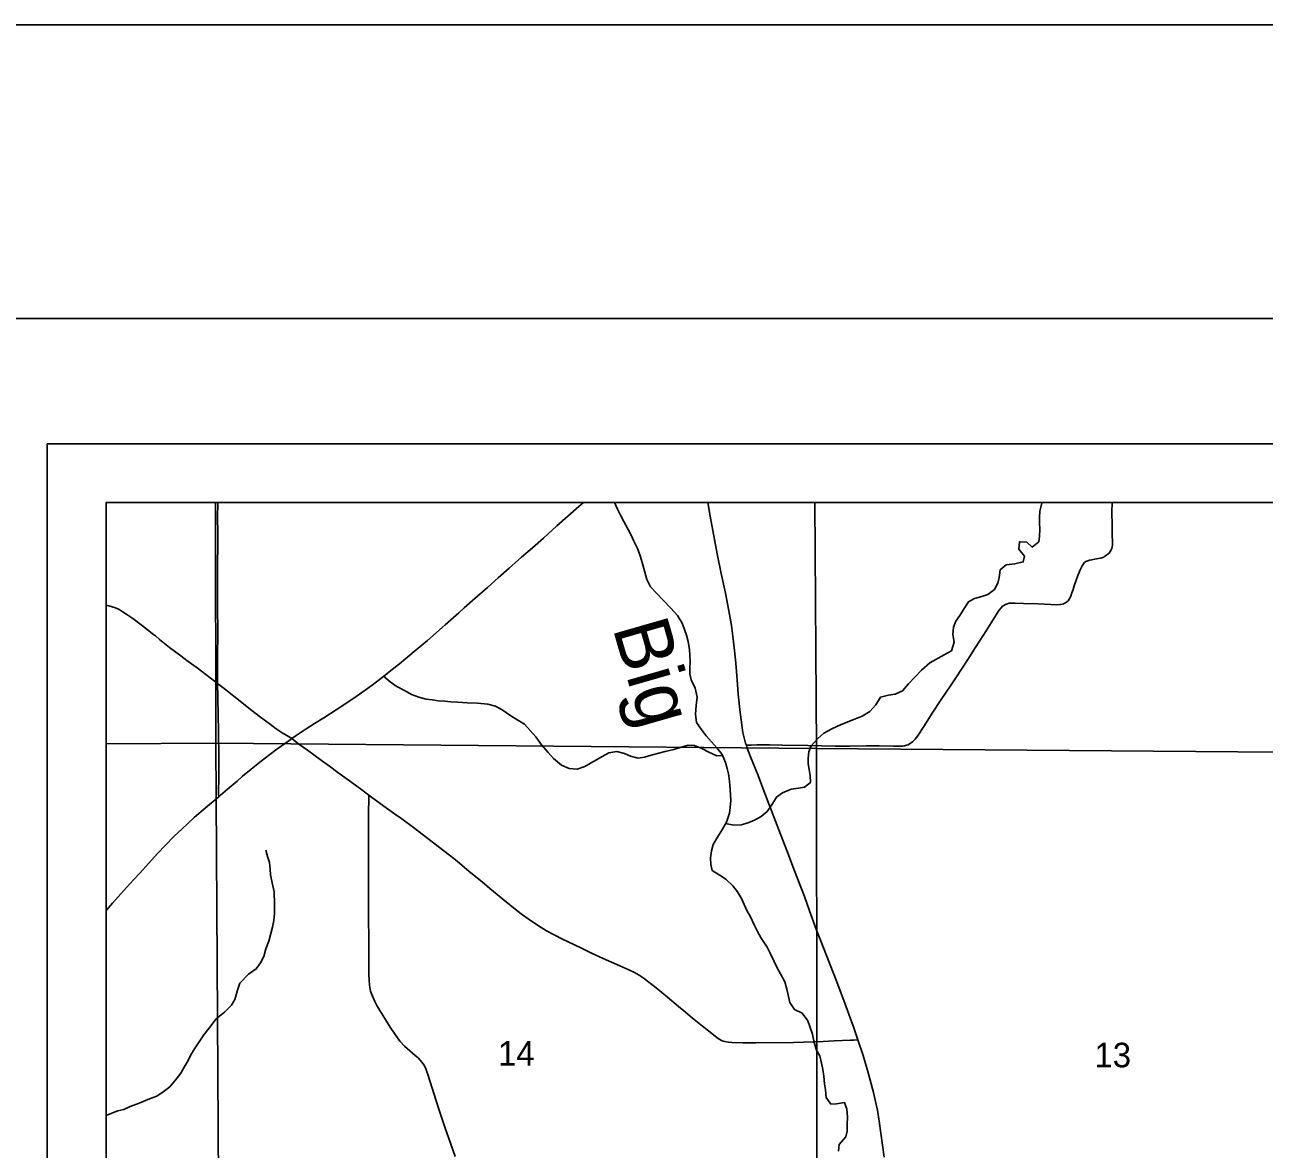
# Model space of a CAD drawing. Extents: x 0 to 34, y 0 to 22.
# Drawn here: x 1.722 to 3.831, y 20.086 to 22 of the extents above; entities that cross this region are included whole.
import ezdxf

# ---------------------------------------------------------------- set-up
doc = ezdxf.new("R2010")
doc.units = 0
for name, color, linetype in [('GM_X_County_Road', 7, 'Continuous'), ('GM_X_County_Road_Text', 7, 'Continuous'), ('GM_X_Interchange_Ramps', 7, 'Continuous'), ('GM_X_State_Location', 7, 'Continuous'), ('GM_X_State_Route', 7, 'Continuous'), ('GM_X_Township_Road_Text', 7, 'Continuous'), ('SH_Border', 7, 'Continuous'), ('SH_Cut_Line', 7, 'Continuous'), ('SH_Data', 7, 'Continuous')]:
    doc.layers.add(name, color=color, linetype=linetype)

msp = doc.modelspace()

# ---------------------------------------------------------------- linework, layer by layer
at = {"layer": 'GM_X_County_Road'}
for points in [[(1.8602, 20.4926), (1.8713, 20.5049), (1.9004, 20.5371), (1.917, 20.5554), (1.9481, 20.5897), (1.9609, 20.6032), (1.9763, 20.6186), (1.9897, 20.6315), (1.9988, 20.64), (2.0102, 20.6505), (2.0218, 20.6608), (2.036, 20.6728), (2.052, 20.6861), (2.055, 20.6886), (2.0667, 20.6986), (2.0832, 20.7127), (2.0926, 20.7208), (2.1069, 20.7327), (2.1239, 20.7463), (2.1387, 20.7577), (2.1511, 20.767), (2.1711, 20.7814), (2.1762, 20.7849), (2.1838, 20.7902), (2.1993, 20.8006), (2.2151, 20.8106), (2.2309, 20.8204), (2.2519, 20.8337), (2.27, 20.8456), (2.2878, 20.858), (2.3129, 20.8761), (2.3351, 20.893), (2.3449, 20.9006), (2.3595, 20.9122), (2.3881, 20.936), (2.407, 20.9522), (2.4373, 20.9788), (2.4513, 20.9911), (2.4606, 20.9993), (2.4699, 21.0075), (2.4837, 21.0198), (2.5091, 21.0423), (2.5277, 21.0586), (2.5463, 21.075), (2.5672, 21.0935), (2.5859, 21.1099), (2.6045, 21.1263), (2.6275, 21.1471), (2.6459, 21.1638), (2.6647, 21.1801), (2.6725, 21.1866)], [(2.9413, 20.8128), (2.9391, 20.8295), (2.936, 20.8604), (2.934, 20.8852), (2.9319, 20.9131), (2.9299, 20.9347), (2.9271, 20.9593), (2.9243, 20.9777), (2.9201, 21.0022), (2.9142, 21.0327), (2.9072, 21.0661), (2.9004, 21.0996), (2.888, 21.1636), (2.884, 21.1866)], [(3.0574, 20.4918), (3.0485, 20.5163), (3.0318, 20.5597), (3.0186, 20.5946), (3.0053, 20.6295), (2.9798, 20.6962), (2.9697, 20.7223), (2.9568, 20.7539), (2.9514, 20.7685), (2.9498, 20.7737), (2.9485, 20.7774), (2.9461, 20.7865), (2.9441, 20.7956), (2.942, 20.8079), (2.9413, 20.8128)], [(3.1397, 20.2723), (3.1327, 20.2924), (3.1158, 20.3391), (3.1025, 20.3739), (3.0812, 20.429), (3.0687, 20.4608), (3.0574, 20.4918)], [(3.1846, 20.0724), (3.1759, 20.1339), (3.1729, 20.1522), (3.1698, 20.1674), (3.1661, 20.1825), (3.1563, 20.2184), (3.1485, 20.2453), (3.1397, 20.2723)]]:
    msp.add_lwpolyline(points, dxfattribs=at)
at = {"layer": 'GM_X_County_Road_Text'}
for points in [[(2.7254, 21.1866), (2.7305, 21.1757), (2.7358, 21.1655), (2.7416, 21.1545), (2.7488, 21.1408), (2.7538, 21.131), (2.7584, 21.1212), (2.7649, 21.1075), (2.7699, 21.0943), (2.7737, 21.0806), (2.7772, 21.0685), (2.7803, 21.056), (2.7868, 21.0431), (2.7974, 21.0321), (2.8081, 21.0208), (2.8214, 21.0068), (2.8325, 20.9947), (2.8405, 20.9814), (2.8443, 20.9708), (2.8481, 20.961), (2.8508, 20.9503), (2.8532, 20.9363), (2.8536, 20.9268), (2.854, 20.9154), (2.8537, 20.9052), (2.8537, 20.8953), (2.856, 20.8847), (2.8625, 20.8707), (2.866, 20.8555), (2.8646, 20.8411), (2.8635, 20.8267), (2.8651, 20.8123), (2.8727, 20.8009), (2.8814, 20.7896), (2.8906, 20.7797), (2.8997, 20.7691), (2.9085, 20.7578), (2.9142, 20.7445), (2.9169, 20.7343), (2.9192, 20.7248), (2.9212, 20.7127), (2.9224, 20.6982), (2.9232, 20.6793), (2.9225, 20.6679), (2.921, 20.658), (2.9158, 20.6428), (2.909, 20.6306), (2.9007, 20.6173), (2.8936, 20.6044), (2.8906, 20.5941), (2.8888, 20.582), (2.8896, 20.5706), (2.8919, 20.5604), (2.9033, 20.5528), (2.9151, 20.5457), (2.9269, 20.5343), (2.9349, 20.5241), (2.9414, 20.5127)], [(2.9145, 20.6405), (2.9283, 20.6376), (2.9416, 20.6384), (2.9526, 20.6414), (2.9628, 20.6453), (2.9753, 20.6522), (2.9851, 20.6609), (2.9934, 20.6723), (3.0013, 20.6853), (3.0111, 20.6929), (3.0262, 20.699), (3.0383, 20.7006), (3.0486, 20.7021), (3.0588, 20.7102), (3.0587, 20.7223), (3.0568, 20.7322), (3.0548, 20.742), (3.0548, 20.7519), (3.0559, 20.7625), (3.0604, 20.7724), (3.0713, 20.7853), (3.0819, 20.7941), (3.0963, 20.8021), (3.1099, 20.8083), (3.1197, 20.8125), (3.133, 20.8175), (3.147, 20.8232), (3.1602, 20.8308), (3.17, 20.8426), (3.1783, 20.8556), (3.1919, 20.859), (3.2029, 20.8606), (3.2158, 20.8663), (3.2259, 20.8781), (3.2369, 20.89), (3.2478, 20.9014), (3.2618, 20.914), (3.2864, 20.9273), (3.2992, 20.9342), (3.3037, 20.949), (3.301, 20.9619), (3.3025, 20.9748), (3.3062, 20.9847), (3.313, 20.9946), (3.3217, 21.0083), (3.3277, 21.0178), (3.3383, 21.0235), (3.3508, 21.027), (3.361, 21.0301), (3.3719, 21.0385), (3.3779, 21.0495), (3.3802, 21.059), (3.382, 21.0723), (3.3918, 21.0807), (3.4066, 21.0823), (3.421, 21.0857), (3.4229, 21.0956), (3.4133, 21.1073), (3.4144, 21.1199), (3.4269, 21.1195), (3.4364, 21.1108), (3.4474, 21.12), (3.4485, 21.1298), (3.4492, 21.1412), (3.4488, 21.1515), (3.4487, 21.1621), (3.4491, 21.172), (3.4528, 21.1857), (3.4535, 21.1866)], [(2.3323, 20.891), (2.3436, 20.8815), (2.3539, 20.8743), (2.3694, 20.8663), (2.3801, 20.8602), (2.3926, 20.8557), (2.4047, 20.8522), (2.4157, 20.8507), (2.4256, 20.8492), (2.4366, 20.8484), (2.4472, 20.8477), (2.459, 20.8469), (2.4746, 20.8461), (2.4924, 20.8454), (2.5099, 20.8438), (2.5228, 20.8404), (2.5345, 20.8339), (2.5493, 20.8237), (2.5611, 20.8165), (2.5725, 20.8096)], [(2.9092, 20.7562), (2.8994, 20.7558), (2.8857, 20.7619), (2.874, 20.7683), (2.8614, 20.7732), (2.8508, 20.7735), (2.8387, 20.7704), (2.8262, 20.7666), (2.8114, 20.7631), (2.8008, 20.7604), (2.788, 20.7566), (2.7766, 20.7535), (2.7656, 20.7519), (2.7524, 20.7549), (2.7425, 20.7594), (2.7292, 20.7628), (2.716, 20.7605), (2.7046, 20.7543), (2.6948, 20.7486), (2.6846, 20.7429), (2.6747, 20.7375), (2.6619, 20.7329), (2.6482, 20.734), (2.6353, 20.7397), (2.6216, 20.751), (2.6125, 20.7612), (2.6011, 20.7744), (2.5915, 20.7881), (2.5725, 20.8096)], [(1.8602, 20.1435), (1.8672, 20.1462), (1.8801, 20.1511), (1.8903, 20.1538), (1.901, 20.1587), (1.9165, 20.1644), (1.934, 20.1716), (1.9465, 20.1761), (1.9575, 20.1837), (1.9686, 20.1921), (1.9796, 20.2054), (1.9872, 20.2152), (1.9933, 20.2255), (1.9997, 20.2369), (2.0047, 20.2464), (2.0108, 20.2566), (2.0267, 20.2805), (2.0351, 20.2912), (2.0477, 20.3079), (2.0617, 20.3192), (2.0739, 20.331), (2.0796, 20.3409), (2.0838, 20.3568), (2.0876, 20.3686), (2.1028, 20.3838), (2.1157, 20.3929), (2.1233, 20.4031), (2.1286, 20.4138), (2.1324, 20.4271), (2.137, 20.44), (2.1408, 20.4533), (2.1435, 20.4639), (2.1458, 20.4753), (2.1469, 20.4874), (2.147, 20.5034), (2.1462, 20.5239), (2.1428, 20.5395), (2.1398, 20.5531), (2.1394, 20.5626), (2.1383, 20.574), (2.1349, 20.5843), (2.1319, 20.5953)], [(2.9414, 20.5127), (2.946, 20.5025), (2.9509, 20.4923), (2.9567, 20.4813), (2.9632, 20.468), (2.9689, 20.4567), (2.975, 20.4453), (2.9853, 20.4302), (2.9906, 20.4196), (2.9968, 20.4067), (3.0025, 20.3946), (3.0078, 20.3847), (3.0151, 20.3707), (3.0193, 20.3563), (3.0217, 20.3461), (3.0236, 20.3358), (3.0316, 20.3241), (3.0449, 20.3177), (3.0544, 20.3045), (3.0579, 20.295), (3.0625, 20.2817), (3.0652, 20.2677), (3.0694, 20.2548), (3.0751, 20.245), (3.0778, 20.2324), (3.0802, 20.2218), (3.0817, 20.2101), (3.0829, 20.1975), (3.0845, 20.1873), (3.0857, 20.174), (3.0937, 20.1627), (3.1031, 20.1631), (3.1168, 20.1654), (3.121, 20.1544), (3.1218, 20.1411), (3.1211, 20.1282), (3.1212, 20.1165), (3.1193, 20.107), (3.108, 20.094), (3.1069, 20.0826)]]:
    msp.add_lwpolyline(points, dxfattribs=at)
at = {"layer": 'GM_X_Interchange_Ramps'}
for points in [[(2.0499, 20.8787), (2.0498, 20.8794), (2.0498, 20.8918), (2.05, 20.9042), (2.05, 20.9321), (2.0503, 20.9569), (2.0502, 20.9816), (2.0501, 20.994), (2.0501, 21.0096), (2.0501, 21.0655), (2.05, 21.0872), (2.0503, 21.1089), (2.0503, 21.1377), (2.0501, 21.1596), (2.0502, 21.1866)], [(2.9498, 20.7737), (2.9583, 20.774), (2.9676, 20.7743), (2.9893, 20.7742), (3.011, 20.7736), (3.0545, 20.773), (3.1011, 20.7722), (3.126, 20.7723), (3.1539, 20.7726), (3.1756, 20.7726), (3.2005, 20.7722), (3.2098, 20.772), (3.216, 20.7723), (3.2191, 20.7728), (3.2221, 20.7735), (3.225, 20.7746), (3.2277, 20.776), (3.2303, 20.7777), (3.2328, 20.7796), (3.235, 20.7817), (3.2371, 20.784), (3.2409, 20.789), (3.2528, 20.8072), (3.2663, 20.8281), (3.2816, 20.8515), (3.2972, 20.8746), (3.3075, 20.8901), (3.3161, 20.9032), (3.3279, 20.9215), (3.3381, 20.9376), (3.3478, 20.9527), (3.358, 20.9684), (3.3665, 20.9821), (3.3747, 20.9955), (3.3797, 21.0031), (3.3834, 21.0077), (3.3859, 21.0101), (3.3882, 21.0116), (3.3908, 21.0131), (3.394, 21.0143), (3.3969, 21.0152), (3.3999, 21.0157), (3.4065, 21.0156), (3.4216, 21.0149), (3.4463, 21.0141), (3.4682, 21.0133), (3.4782, 21.0127), (3.4839, 21.0132), (3.487, 21.0138), (3.4897, 21.0144), (3.4931, 21.0159), (3.4952, 21.0176), (3.4973, 21.0195), (3.4993, 21.0221), (3.5008, 21.0249), (3.5019, 21.0276), (3.5039, 21.0333), (3.506, 21.039), (3.5078, 21.045), (3.5139, 21.0625), (3.5185, 21.0736), (3.5201, 21.0767), (3.5214, 21.0792), (3.523, 21.082), (3.5253, 21.0845), (3.5278, 21.0862), (3.531, 21.0877), (3.5338, 21.0888), (3.5378, 21.0895), (3.5427, 21.0906), (3.552, 21.0919), (3.555, 21.0927), (3.5579, 21.094), (3.56, 21.0955), (3.5628, 21.0973), (3.5653, 21.0993), (3.5671, 21.1008), (3.569, 21.1032), (3.5707, 21.1062), (3.5719, 21.1085), (3.5723, 21.1112), (3.5727, 21.1144), (3.5727, 21.1209), (3.5723, 21.13), (3.5722, 21.1487), (3.5719, 21.1699), (3.5721, 21.1866)], [(1.8602, 21.0121), (1.865, 21.0111), (1.8709, 21.0095), (1.8763, 21.0077), (1.8827, 21.0046), (1.8879, 21.0014), (1.8955, 20.9964), (1.9058, 20.9892), (1.9201, 20.9787), (1.9297, 20.971), (1.9395, 20.9635), (1.9444, 20.9597), (1.9514, 20.9536), (1.9683, 20.9402), (1.9854, 20.9275), (2.0002, 20.9164), (2.015, 20.9053), (2.0298, 20.8942), (2.0396, 20.8867), (2.0499, 20.8787)], [(2.052, 20.6861), (2.0518, 20.6922), (2.0518, 20.7016), (2.0519, 20.7108), (2.0519, 20.7217), (2.052, 20.7369), (2.0519, 20.7524), (2.0519, 20.7679), (2.0515, 20.7819), (2.0514, 20.7988), (2.0512, 20.8236), (2.0506, 20.8547), (2.0499, 20.8787)], [(2.0499, 20.8787), (2.0589, 20.8717), (2.0857, 20.8507), (2.103, 20.8368), (2.1206, 20.823), (2.1421, 20.807), (2.1496, 20.8015), (2.16, 20.7946), (2.1707, 20.7883), (2.1762, 20.7849)], [(2.1762, 20.7849), (2.1885, 20.7756), (2.2031, 20.7652), (2.214, 20.7575), (2.227, 20.7479), (2.2402, 20.7382), (2.2548, 20.7275), (2.2708, 20.7161), (2.2846, 20.7059), (2.2957, 20.6976), (2.3074, 20.6885)], [(2.4545, 20.0735), (2.443, 20.1057), (2.4379, 20.1203), (2.4329, 20.1355), (2.4261, 20.1561), (2.4188, 20.179), (2.4115, 20.2005), (2.4071, 20.215), (2.4045, 20.2231), (2.4013, 20.2292), (2.3978, 20.2342), (2.3945, 20.2378), (2.3911, 20.2416), (2.3864, 20.2457), (2.3769, 20.2534), (2.3681, 20.2612), (2.3603, 20.27), (2.3512, 20.2829), (2.3439, 20.2937), (2.3344, 20.3084), (2.3261, 20.3222), (2.321, 20.3306), (2.3174, 20.3374), (2.3135, 20.3463), (2.3105, 20.3549), (2.3086, 20.3654), (2.3078, 20.3746), (2.3072, 20.3841), (2.3073, 20.4452), (2.3068, 20.4781), (2.3067, 20.5043), (2.3067, 20.5204), (2.3067, 20.5447), (2.307, 20.5632), (2.3071, 20.6004), (2.307, 20.6223), (2.3066, 20.6567), (2.3073, 20.6847), (2.3074, 20.6885)], [(2.3074, 20.6885), (2.3117, 20.6852), (2.3393, 20.6652), (2.3512, 20.6569), (2.3633, 20.6483), (2.3832, 20.6334), (2.4079, 20.6147), (2.4251, 20.6014), (2.4447, 20.5863), (2.4519, 20.5806), (2.4616, 20.5729), (2.4783, 20.559), (2.5, 20.5414), (2.5134, 20.53), (2.526, 20.5195), (2.5355, 20.5116), (2.5474, 20.5019), (2.5591, 20.4923), (2.5691, 20.4847), (2.5747, 20.481), (2.5802, 20.4769), (2.5964, 20.466), (2.6096, 20.4579), (2.6229, 20.4509), (2.637, 20.4438), (2.6553, 20.435), (2.6717, 20.4273), (2.6865, 20.4199), (2.7059, 20.4109), (2.7346, 20.3983), (2.7496, 20.3914), (2.7594, 20.3866), (2.7673, 20.3821), (2.7741, 20.3776), (2.7841, 20.3703), (2.7962, 20.3607), (2.8154, 20.3449), (2.8345, 20.3292), (2.8465, 20.3193), (2.8584, 20.3093), (2.8752, 20.2954), (2.8824, 20.2896), (2.8945, 20.2799), (2.902, 20.2743), (2.9046, 20.2727), (2.9074, 20.2713), (2.9102, 20.2701), (2.9132, 20.2692), (2.9162, 20.2685), (2.9193, 20.268), (2.9254, 20.2674), (2.944, 20.2671), (2.9658, 20.2671), (3.0299, 20.2676), (3.0803, 20.2696), (3.099, 20.2703), (3.1268, 20.2715), (3.133, 20.2719), (3.1397, 20.2723)]]:
    msp.add_lwpolyline(points, dxfattribs=at)
at = {"layer": 'GM_X_State_Route'}
for points in [[(2.0467, 21.1866), (1.8602, 21.1866), (1.8602, 20.776), (2.0472, 20.7772)], [(3.0663, 21.1866), (2.0467, 21.1866), (2.0472, 20.7772), (3.0692, 20.7682)], [(4.068, 21.1866), (3.0663, 21.1866), (3.0692, 20.7682), (4.0731, 20.7603)], [(1.8602, 20.776), (1.8602, 19.7485), (2.0531, 19.7487), (2.0472, 20.7772)], [(2.0472, 20.7772), (3.0692, 20.7682), (3.0705, 19.7579), (2.0531, 19.7487)], [(3.0692, 20.7682), (4.0731, 20.7603), (4.0736, 20.7285), (4.0835, 19.7451), (3.0705, 19.7579)]]:
    msp.add_lwpolyline(points, close=True, dxfattribs=at)
at = {"layer": 'SH_Border'}
msp.add_lwpolyline([(1.5, 21.5), (33.5, 21.5), (33.5, 0.5), (1.5, 0.5)], close=True, dxfattribs=at)
at = {"layer": 'SH_Cut_Line'}
msp.add_lwpolyline([(0, 0), (34, 0), (34, 22), (0, 22)], close=True, dxfattribs=at)
at = {"layer": 'SH_Data'}
for points in [[(1.7602, 21.2866), (8.7602, 21.2866), (8.7602, 14.2866), (1.7602, 14.2866)], [(1.8602, 21.1866), (8.6602, 21.1866), (8.6602, 14.3866), (1.8602, 14.3866)]]:
    msp.add_lwpolyline(points, close=True, dxfattribs=at)

# ---------------------------------------------------------------- texts
at = {"layer": 'GM_X_State_Location'}
for s, p in [('14', (2.5272, 20.2282)), ('13', (3.5422, 20.2254))]:
    msp.add_text(s, height=0.04186, rotation=0, dxfattribs=at).set_placement(p)
at = {"layer": 'GM_X_Township_Road_Text'}
msp.add_text('Big', height=0.09472, rotation=286.0669, dxfattribs=at).set_placement((2.7219, 20.9737))

doc.saveas('drawing.dxf')
